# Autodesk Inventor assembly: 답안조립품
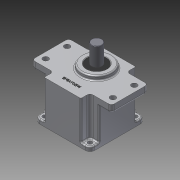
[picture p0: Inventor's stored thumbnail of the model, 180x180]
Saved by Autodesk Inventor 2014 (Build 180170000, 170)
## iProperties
Created: 2015-07
Part Number: 답안조립품
Document SubType Name: Assembly
Designer: Administrator
Author: Administrator
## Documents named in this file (12)
- C:\Users\Administrator\Desktop\450727V1006\답안조립품.iam
- C:\Users\Administrator\Desktop\450727V1006\본체.ipt
- C:\Users\Administrator\Desktop\450727V1006\오일실 17x32x8.ipt
- C:\Users\Administrator\Desktop\450727V1006\베어링 6003.ipt
- 베어링 6003.ipt
- C:\Users\Administrator\Desktop\450727V1006\베어링 608.ipt
- 베어링 608.ipt
- C:\Users\Administrator\Desktop\450727V1006\서브축.ipt
- C:\Users\Administrator\Desktop\450727V1006\메인축.ipt
- C:\Users\Administrator\Desktop\450727V1006\커버.ipt
- C:\Users\Administrator\Desktop\450727V1006\오일실 8x22x7.ipt
- C:\Users\Administrator\Desktop\450727V1006\M4x0.5x16.ipt
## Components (4 placed, 1 different names)
1. M4x0.5x12:1
2. M4x0.5x12:2
3. M4x0.5x12:3
4. M4x0.5x12:4
